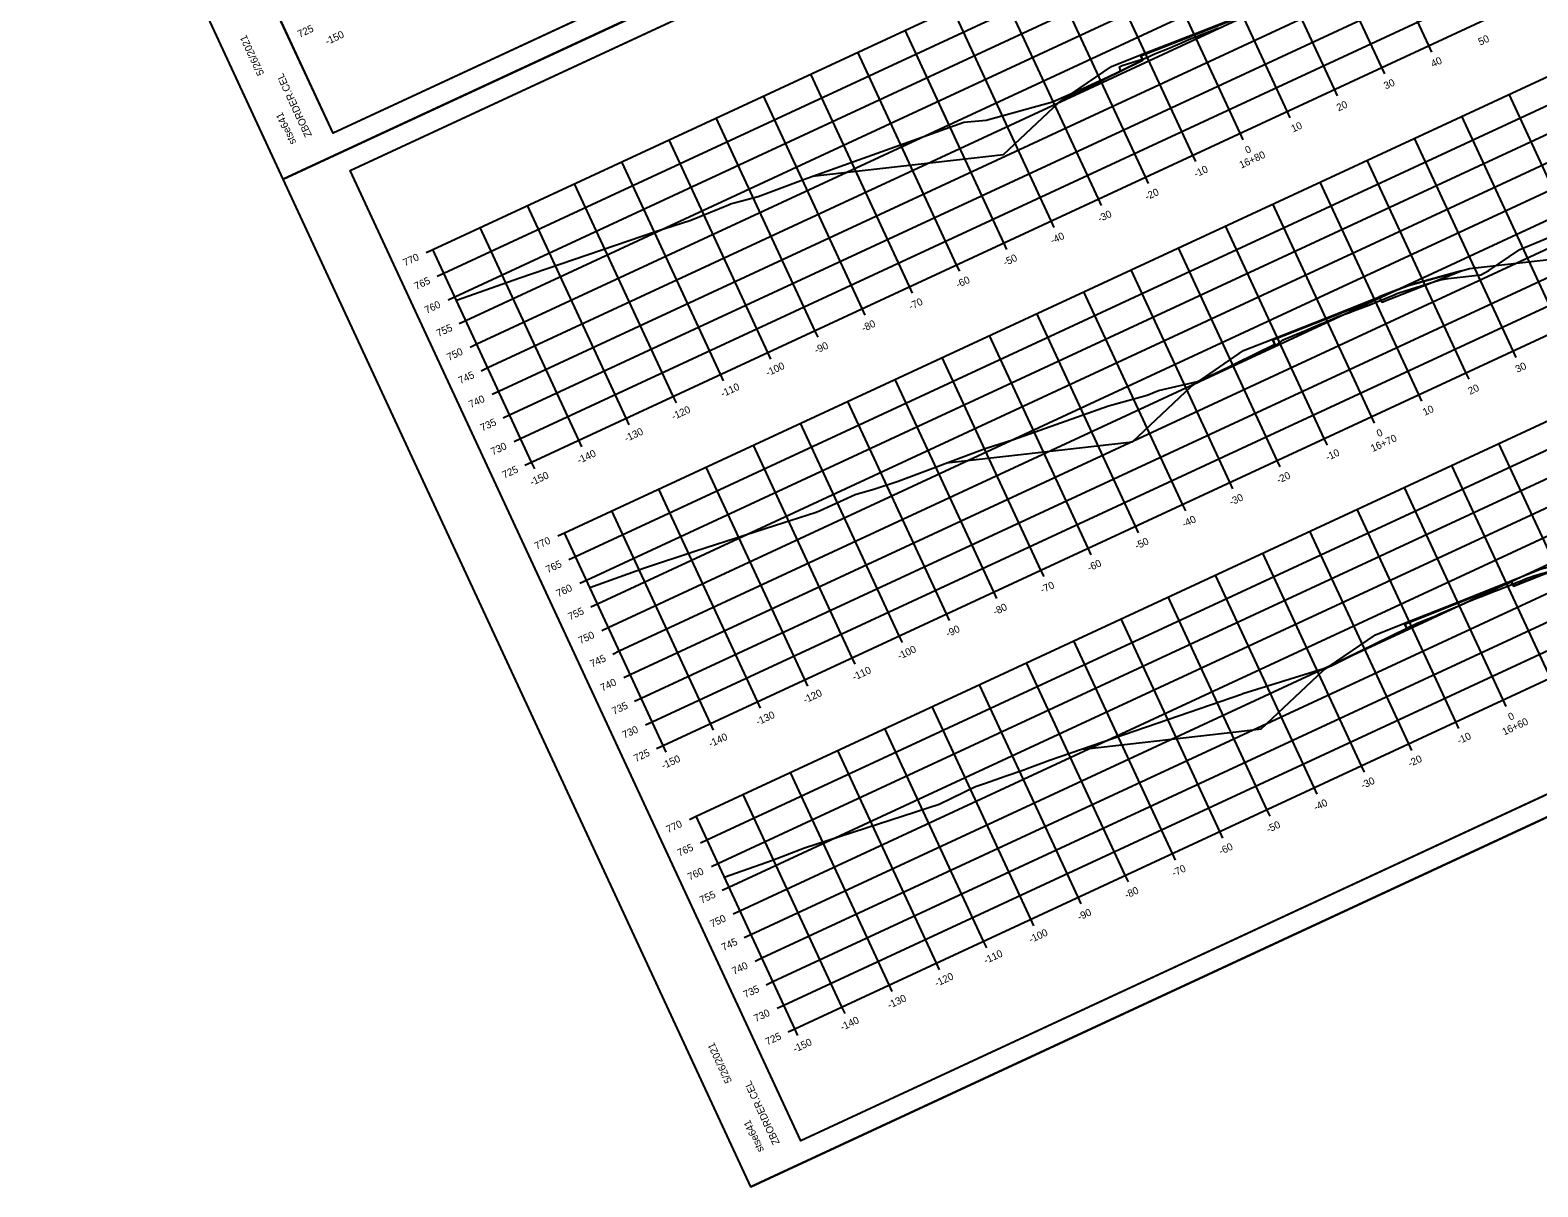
# Model space of a CAD drawing. Extents: x 1354696 to 1366163, y 660729 to 670380.
# Drawn here: x 1358133.8 to 1358423.4, y 665349.1 to 665571.2 of the extents above; entities that cross this region are included whole.
import ezdxf

# ---------------------------------------------------------------- set-up
doc = ezdxf.new("R2010")
doc.units = 0
for name, color, linetype in [('Default', 7, 'Continuous'), ('R_Alt Surface', 7, 'Continuous'), ('R_Axis', 7, 'Continuous'), ('R_Axis Annot', 7, 'Continuous'), ('R_Border', 7, 'Continuous'), ('R_Exist Surface', 7, 'Continuous'), ('R_Fin Surface', 7, 'Continuous'), ('R_Grid', 7, 'Continuous'), ('R_No Plot', 7, 'Continuous')]:
    doc.layers.add(name, color=color, linetype=linetype)

msp = doc.modelspace()

# ---------------------------------------------------------------- linework, layer by layer
at = {"layer": 'Default'}
for points in [[(1358347.17, 665566.29), (1358347.56, 665565.42), (1358332.31, 665557.97), (1358341.5, 665564.25), (1358347.1, 665566.45)], [(1358393.01, 665519.8), (1358393.42, 665518.94), (1358408.71, 665524.98), (1358398.53, 665522.17), (1358392.94, 665519.96)], [(1358372.51, 665511.72), (1358372.9, 665510.85), (1358357.75, 665503.44), (1358366.85, 665509.66), (1358372.44, 665511.87)], [(1358418.73, 665464.43), (1358418.32, 665465.29), (1358418.25, 665465.44), (1358423.83, 665467.67), (1358433.77, 665470.41)], [(1358397.84, 665457.15), (1358398.23, 665456.28), (1358383.18, 665448.92), (1358392.19, 665455.08), (1358397.77, 665457.3)]]:
    msp.add_lwpolyline(points, close=True, dxfattribs=at)
at = {"layer": 'R_Alt Surface'}
for points in [[(1358332.31, 665557.97), (1358347.56, 665565.42), (1358347.17, 665566.29), (1358357.43, 665570.31), (1358367.69, 665574.33), (1358368.1, 665573.47), (1358383.66, 665579.56)], [(1358357.75, 665503.44), (1358372.9, 665510.85), (1358372.51, 665511.72), (1358382.76, 665515.76), (1358393.01, 665519.8), (1358393.42, 665518.94), (1358408.71, 665524.98)], [(1358383.18, 665448.92), (1358398.23, 665456.28), (1358397.84, 665457.15), (1358408.08, 665461.22), (1358418.32, 665465.29), (1358418.73, 665464.43), (1358433.77, 665470.41)]]:
    msp.add_lwpolyline(points, dxfattribs=at)
at = {"layer": 'R_Axis'}
for p, q in [((1358230.15, 665488.26), (1358502.25, 665614.59)), ((1358403.07, 665567), (1358402.48, 665568.27)), ((1358394, 665562.79), (1358393.41, 665564.06)), ((1358255.41, 665433.84), (1358527.52, 665560.17)), ((1358384.93, 665558.58), (1358384.34, 665559.85)), ((1358375.86, 665554.37), (1358375.27, 665555.64)), ((1358366.79, 665550.16), (1358366.2, 665551.43)), ((1358357.72, 665545.95), (1358357.13, 665547.22)), ((1358348.65, 665541.74), (1358348.06, 665543.01)), ((1358339.58, 665537.53), (1358338.99, 665538.8)), ((1358330.51, 665533.31), (1358329.92, 665534.58)), ((1358209.93, 665528.49), (1358211.2, 665529.08)), ((1358230.15, 665488.26), (1358211.2, 665529.08)), ((1358321.44, 665529.1), (1358320.85, 665530.37)), ((1358312.37, 665524.89), (1358311.78, 665526.16)), ((1358212.03, 665523.95), (1358213.3, 665524.54)), ((1358214.14, 665519.42), (1358215.41, 665520.01)), ((1358303.3, 665520.68), (1358302.71, 665521.95)), ((1358294.23, 665516.47), (1358293.64, 665517.74)), ((1358216.24, 665514.88), (1358217.51, 665515.47)), ((1358218.35, 665510.35), (1358219.62, 665510.94)), ((1358285.16, 665512.26), (1358284.57, 665513.53)), ((1358276.09, 665508.05), (1358275.5, 665509.32)), ((1358419.26, 665508.37), (1358418.67, 665509.64)), ((1358220.45, 665505.81), (1358221.72, 665506.4)), ((1358267.02, 665503.84), (1358266.43, 665505.11)), ((1358280.68, 665379.42), (1358552.78, 665505.75)), ((1358410.19, 665504.16), (1358409.6, 665505.43)), ((1358222.56, 665501.28), (1358223.83, 665501.87)), ((1358257.95, 665499.63), (1358257.36, 665500.9)), ((1358401.12, 665499.95), (1358400.53, 665501.22)), ((1358224.66, 665496.74), (1358225.93, 665497.33)), ((1358248.88, 665495.42), (1358248.29, 665496.69)), ((1358392.05, 665495.74), (1358391.46, 665497.01)), ((1358226.77, 665492.21), (1358228.04, 665492.8)), ((1358239.81, 665491.2), (1358239.22, 665492.47)), ((1358382.98, 665491.53), (1358382.39, 665492.8)), ((1358228.88, 665487.67), (1358230.15, 665488.26)), ((1358230.74, 665486.99), (1358230.15, 665488.26)), ((1358373.91, 665487.32), (1358373.32, 665488.59)), ((1358364.84, 665483.1), (1358364.25, 665484.37)), ((1358355.77, 665478.89), (1358355.18, 665480.16)), ((1358346.7, 665474.68), (1358346.11, 665475.95)), ((1358235.19, 665474.07), (1358236.46, 665474.66)), ((1358255.41, 665433.84), (1358236.46, 665474.66)), ((1358237.3, 665469.53), (1358238.57, 665470.12)), ((1358337.63, 665470.47), (1358337.04, 665471.74)), ((1358328.56, 665466.26), (1358327.97, 665467.53)), ((1358239.4, 665465), (1358240.67, 665465.59)), ((1358319.49, 665462.05), (1358318.9, 665463.32)), ((1358241.51, 665460.46), (1358242.78, 665461.05)), ((1358310.42, 665457.84), (1358309.83, 665459.11)), ((1358243.61, 665455.93), (1358244.88, 665456.52)), ((1358301.35, 665453.63), (1358300.76, 665454.9)), ((1358245.72, 665451.39), (1358246.99, 665451.98)), ((1358292.28, 665449.42), (1358291.69, 665450.69)), ((1358247.83, 665446.86), (1358249.1, 665447.45)), ((1358283.21, 665445.21), (1358282.62, 665446.48)), ((1358249.93, 665442.32), (1358251.2, 665442.91)), ((1358274.14, 665440.99), (1358273.55, 665442.26)), ((1358417.32, 665441.32), (1358416.73, 665442.59)), ((1358252.04, 665437.79), (1358253.31, 665438.38)), ((1358408.25, 665437.11), (1358407.66, 665438.38)), ((1358265.07, 665436.78), (1358264.48, 665438.05)), ((1358254.14, 665433.25), (1358255.41, 665433.84)), ((1358256, 665432.57), (1358255.41, 665433.84)), ((1358399.18, 665432.89), (1358398.59, 665434.16)), ((1358390.11, 665428.68), (1358389.52, 665429.95)), ((1358381.04, 665424.47), (1358380.45, 665425.74)), ((1358371.97, 665420.26), (1358371.38, 665421.53)), ((1358260.46, 665419.65), (1358261.73, 665420.24)), ((1358280.68, 665379.42), (1358261.73, 665420.24)), ((1358262.56, 665415.11), (1358263.83, 665415.7)), ((1358362.9, 665416.05), (1358362.31, 665417.32)), ((1358353.83, 665411.84), (1358353.24, 665413.11)), ((1358264.67, 665410.58), (1358265.94, 665411.17)), ((1358266.77, 665406.04), (1358268.04, 665406.63)), ((1358344.76, 665407.63), (1358344.17, 665408.9)), ((1358335.69, 665403.42), (1358335.1, 665404.69)), ((1358268.88, 665401.51), (1358270.15, 665402.1)), ((1358326.62, 665399.21), (1358326.03, 665400.48)), ((1358270.99, 665396.97), (1358272.26, 665397.56)), ((1358317.55, 665395), (1358316.96, 665396.27)), ((1358273.09, 665392.44), (1358274.36, 665393.03)), ((1358308.48, 665390.78), (1358307.89, 665392.05)), ((1358275.2, 665387.9), (1358276.47, 665388.49)), ((1358299.41, 665386.57), (1358298.82, 665387.84)), ((1358277.3, 665383.37), (1358278.57, 665383.96)), ((1358290.34, 665382.36), (1358289.75, 665383.63)), ((1358279.41, 665378.83), (1358280.68, 665379.42)), ((1358281.27, 665378.15), (1358280.68, 665379.42))]:
    msp.add_line(p, q, dxfattribs=at)
at = {"layer": 'R_Border'}
for p, q in [((1358192.01, 665551.41), (1358105.49, 665737.77)), ((1358478.79, 665684.56), (1358192.01, 665551.41)), ((1358195.32, 665544.27), (1358482.1, 665677.41)), ((1358192.01, 665551.41), (1358192.01, 665551.41)), ((1358281.84, 665357.91), (1358195.32, 665544.27)), ((1358568.62, 665491.06), (1358281.84, 665357.91)), ((1358281.84, 665357.91), (1358281.84, 665357.91))]:
    msp.add_line(p, q, dxfattribs=at)
at = {"layer": 'R_Exist Surface'}
for points in [[(1358215.7, 665519.38), (1358227.87, 665523.63), (1358253.93, 665532.54), (1358260.75, 665534.73), (1358267.94, 665537.66), (1358268.36, 665537.85), (1358269.04, 665538.06), (1358273.67, 665539.28), (1358282.39, 665542.55), (1358313.18, 665553.52), (1358317.48, 665553.9), (1358330.2, 665557.41), (1358336.15, 665560.04), (1358343.27, 665563.31), (1358343.05, 665564.14), (1358343.55, 665564.41), (1358347.84, 665565.78), (1358348.61, 665566.1), (1358349.26, 665566.43), (1358350, 665566.71), (1358352.58, 665567.74), (1358353.75, 665568.23), (1358354.94, 665568.74), (1358356.5, 665569.44), (1358357.69, 665569.94), (1358359.28, 665570.58), (1358360.5, 665571.03), (1358362.08, 665571.67)], [(1358241.33, 665464.17), (1358251.85, 665467.97), (1358261.71, 665471.19), (1358276.78, 665476.05), (1358284.79, 665478.65), (1358285.56, 665478.96), (1358292.3, 665482), (1358296.05, 665483.13), (1358300.56, 665484.59), (1358317.26, 665490.89), (1358322.72, 665492.58), (1358340.92, 665499.08), (1358348.38, 665501.13), (1358350.53, 665501.99), (1358358.04, 665503.76), (1358372.98, 665510.66), (1358373.34, 665510.84), (1358374.47, 665511.75), (1358374.6, 665511.82), (1358376.17, 665512.43), (1358376.57, 665512.6), (1358379.09, 665513.66), (1358379.34, 665513.77), (1358381.85, 665514.85), (1358382.1, 665514.96), (1358384.61, 665516.02), (1358384.87, 665516.13), (1358387.43, 665517.07), (1358387.7, 665517.18), (1358390.24, 665518.14), (1358390.63, 665518.29), (1358394.39, 665519.81), (1358395.79, 665520.39), (1358396.31, 665520.6), (1358396.68, 665520.75), (1358397.91, 665521.12), (1358403.2, 665522.81), (1358404.66, 665523.23), (1358406.19, 665523.51), (1358412.44, 665524.23), (1358413.96, 665525.07), (1358419.96, 665529.06), (1358440.81, 665537.78)], [(1358267.16, 665408.54), (1358276.39, 665411.82), (1358282.57, 665414.19), (1358308.44, 665422.56), (1358315.39, 665425.97), (1358316.76, 665426.39), (1358317.3, 665426.6), (1358321.07, 665427.95), (1358324.68, 665429.17), (1358325.35, 665429.39), (1358329.62, 665431), (1358366.68, 665443.78), (1358366.72, 665443.79), (1358366.72, 665443.79), (1358383.04, 665448.87), (1358383.72, 665449.11), (1358385.52, 665450.03), (1358398.44, 665456.4), (1358398.64, 665456.55), (1358399.81, 665457.14), (1358400.2, 665457.29), (1358403.73, 665458.76), (1358404.37, 665459.03), (1358406.48, 665459.92), (1358407.13, 665460.21), (1358409.22, 665461.11), (1358409.89, 665461.39), (1358412, 665462.23), (1358412.69, 665462.49), (1358414.78, 665463.33), (1358415.48, 665463.6), (1358418.38, 665464.74), (1358419.45, 665465.17), (1358420.02, 665465.41), (1358421.35, 665465.97), (1358422.83, 665466.45), (1358430.36, 665468.61)]]:
    msp.add_lwpolyline(points, dxfattribs=at)
at = {"layer": 'R_Fin Surface'}
for points in [[(1358284.04, 665543.14), (1358320.77, 665547.3), (1358331.46, 665557.39), (1358332.31, 665557.97), (1358341.5, 665564.25), (1358347.1, 665566.45), (1358357.36, 665570.46), (1358367.62, 665574.48), (1358373.22, 665576.68), (1358383.66, 665579.56), (1358384.94, 665579.92), (1358399.64, 665581.58), (1358408.22, 665589.67)], [(1358309.93, 665488.13), (1358310.38, 665488.18), (1358318.89, 665489.14), (1358320.62, 665489.34), (1358345.54, 665492.17), (1358356.8, 665502.8), (1358357.75, 665503.44), (1358366.85, 665509.66), (1358372.44, 665511.87), (1358382.69, 665515.91), (1358392.94, 665519.96), (1358398.53, 665522.17), (1358408.71, 665524.98), (1358410.25, 665525.4), (1358426.1, 665527.2), (1358434.53, 665535.15)], [(1358335.69, 665433.1), (1358336.72, 665433.22), (1358365.98, 665436.53), (1358370.28, 665437.02), (1358382.14, 665448.21), (1358382.14, 665448.21), (1358383.18, 665448.92), (1358392.19, 665455.08), (1358397.77, 665457.3), (1358408.01, 665461.37), (1358418.25, 665465.44), (1358423.83, 665467.67), (1358433.77, 665470.41), (1358435.56, 665470.9), (1358435.56, 665470.9), (1358452.6, 665472.84), (1358461.11, 665480.87)]]:
    msp.add_lwpolyline(points, dxfattribs=at)
at = {"layer": 'R_Grid'}
for p, q in [((1358211.2, 665529.08), (1358483.3, 665655.41)), ((1358213.3, 665524.54), (1358485.41, 665650.87)), ((1358215.41, 665520.01), (1358487.51, 665646.34)), ((1358217.51, 665515.47), (1358489.62, 665641.8)), ((1358219.62, 665510.94), (1358491.72, 665637.27)), ((1358221.72, 665506.4), (1358493.83, 665632.73)), ((1358223.83, 665501.87), (1358495.93, 665628.2)), ((1358225.93, 665497.33), (1358498.04, 665623.66)), ((1358228.04, 665492.8), (1358500.14, 665619.13)), ((1358230.15, 665488.26), (1358502.25, 665614.59)), ((1358402.48, 665568.27), (1358383.53, 665609.09)), ((1358393.41, 665564.06), (1358374.46, 665604.88)), ((1358236.46, 665474.66), (1358508.57, 665600.99)), ((1358384.34, 665559.85), (1358365.39, 665600.67)), ((1358238.57, 665470.12), (1358510.67, 665596.45)), ((1358375.27, 665555.64), (1358356.32, 665596.46)), ((1358240.67, 665465.59), (1358512.78, 665591.92)), ((1358366.2, 665551.43), (1358347.25, 665592.24)), ((1358242.78, 665461.05), (1358514.88, 665587.38)), ((1358357.13, 665547.22), (1358338.18, 665588.03)), ((1358348.06, 665543.01), (1358329.11, 665583.82)), ((1358244.88, 665456.52), (1358516.99, 665582.85)), ((1358246.99, 665451.98), (1358519.09, 665578.31)), ((1358338.99, 665538.8), (1358320.04, 665579.61)), ((1358329.92, 665534.58), (1358310.97, 665575.4)), ((1358249.1, 665447.45), (1358521.2, 665573.78)), ((1358251.2, 665442.91), (1358523.3, 665569.24)), ((1358320.85, 665530.37), (1358301.9, 665571.19)), ((1358311.78, 665526.16), (1358292.83, 665566.98)), ((1358253.31, 665438.38), (1358525.41, 665564.71)), ((1358302.71, 665521.95), (1358283.76, 665562.77)), ((1358255.41, 665433.84), (1358527.52, 665560.17)), ((1358293.64, 665517.74), (1358274.69, 665558.56)), ((1358436.81, 665518.06), (1358417.86, 665558.88)), ((1358284.57, 665513.53), (1358265.62, 665554.34)), ((1358427.74, 665513.85), (1358408.79, 665554.67)), ((1358275.5, 665509.32), (1358256.55, 665550.13)), ((1358418.67, 665509.64), (1358399.72, 665550.46)), ((1358266.43, 665505.11), (1358247.48, 665545.92)), ((1358261.73, 665420.24), (1358533.83, 665546.57)), ((1358409.6, 665505.43), (1358390.65, 665546.25)), ((1358257.36, 665500.9), (1358238.41, 665541.71)), ((1358263.83, 665415.7), (1358535.94, 665542.03)), ((1358400.53, 665501.22), (1358381.58, 665542.03)), ((1358248.29, 665496.69), (1358229.34, 665537.5)), ((1358265.94, 665411.17), (1358538.04, 665537.5)), ((1358391.46, 665497.01), (1358372.51, 665537.82)), ((1358239.22, 665492.47), (1358220.27, 665533.29)), ((1358268.04, 665406.63), (1358540.15, 665532.96)), ((1358382.39, 665492.8), (1358363.44, 665533.61)), ((1358230.15, 665488.26), (1358211.2, 665529.08)), ((1358270.15, 665402.1), (1358542.25, 665528.43)), ((1358373.32, 665488.59), (1358354.37, 665529.4)), ((1358364.25, 665484.37), (1358345.3, 665525.19)), ((1358272.26, 665397.56), (1358544.36, 665523.89)), ((1358274.36, 665393.03), (1358546.47, 665519.36)), ((1358355.18, 665480.16), (1358336.23, 665520.98)), ((1358346.11, 665475.95), (1358327.16, 665516.77)), ((1358276.47, 665388.49), (1358548.57, 665514.82)), ((1358337.04, 665471.74), (1358318.09, 665512.56)), ((1358278.57, 665383.96), (1358550.68, 665510.29)), ((1358327.97, 665467.53), (1358309.02, 665508.35)), ((1358280.68, 665379.42), (1358552.78, 665505.75)), ((1358318.9, 665463.32), (1358299.95, 665504.14)), ((1358309.83, 665459.11), (1358290.88, 665499.92)), ((1358300.76, 665454.9), (1358281.81, 665495.71)), ((1358291.69, 665450.69), (1358272.74, 665491.5)), ((1358434.87, 665451.01), (1358415.92, 665491.82)), ((1358425.8, 665446.8), (1358406.85, 665487.61)), ((1358282.62, 665446.48), (1358263.67, 665487.29)), ((1358273.55, 665442.26), (1358254.6, 665483.08)), ((1358416.73, 665442.59), (1358397.78, 665483.4)), ((1358264.48, 665438.05), (1358245.53, 665478.87)), ((1358407.66, 665438.38), (1358388.71, 665479.19)), ((1358255.41, 665433.84), (1358236.46, 665474.66)), ((1358398.59, 665434.16), (1358379.64, 665474.98)), ((1358389.52, 665429.95), (1358370.57, 665470.77)), ((1358380.45, 665425.74), (1358361.5, 665466.56)), ((1358371.38, 665421.53), (1358352.43, 665462.35)), ((1358362.31, 665417.32), (1358343.36, 665458.14)), ((1358353.24, 665413.11), (1358334.29, 665453.93)), ((1358344.17, 665408.9), (1358325.22, 665449.71)), ((1358335.1, 665404.69), (1358316.15, 665445.5)), ((1358326.03, 665400.48), (1358307.08, 665441.29)), ((1358316.96, 665396.27), (1358298.01, 665437.08)), ((1358307.89, 665392.05), (1358288.94, 665432.87)), ((1358298.82, 665387.84), (1358279.87, 665428.66)), ((1358289.75, 665383.63), (1358270.8, 665424.45)), ((1358280.68, 665379.42), (1358261.73, 665420.24))]:
    msp.add_line(p, q, dxfattribs=at)
at = {"layer": 'R_No Plot'}
for p, q in [((1358182.43, 665542.58), (1358484.77, 665682.95)), ((1358182.44, 665542.58), (1358484.77, 665682.95)), ((1358272.27, 665349.08), (1358574.61, 665489.45))]:
    msp.add_line(p, q, dxfattribs=at)
for points in [[(1358092.59, 665736.08), (1358394.94, 665876.45), (1358484.77, 665682.95), (1358182.43, 665542.58)], [(1358317.66, 665836.27), (1358335.45, 665844.53), (1358339.61, 665835.57), (1358354.23, 665842.36), (1358375.27, 665852.13), (1358387.23, 665826.64), (1358408.28, 665836.41), (1358478.79, 665684.56), (1358192.01, 665551.41), (1358105.49, 665737.77)], [(1358182.43, 665542.58), (1358484.77, 665682.95), (1358574.61, 665489.45), (1358272.27, 665349.08)], [(1358407.49, 665642.77), (1358425.29, 665651.03), (1358429.45, 665642.07), (1358444.06, 665648.86), (1358465.1, 665658.63), (1358477.07, 665633.14), (1358498.12, 665642.91), (1358568.62, 665491.06), (1358281.84, 665357.91), (1358195.32, 665544.27)]]:
    msp.add_lwpolyline(points, close=True, dxfattribs=at)

# ---------------------------------------------------------------- texts
at = {"layer": 'R_Axis Annot'}
for s, p in [('725', (1358185.6, 665569.72)), ('-150', (1358190.89, 665568.32)), ('50', (1358412.33, 665568.22)), ('40', (1358403.26, 665564.01)), ('30', (1358394.19, 665559.79)), ('20', (1358385.12, 665555.58)), ('10', (1358376.41, 665551.54)), ('0', (1358367.55, 665547.43)), ('16+80', (1358366.44, 665544.59)), ('-10', (1358357.75, 665542.88)), ('-20', (1358348.32, 665538.5)), ('-30', (1358339.25, 665534.29)), ('-40', (1358330.18, 665530.08)), ('770', (1358205.84, 665525.82)), ('-50', (1358321.11, 665525.87)), ('765', (1358208, 665521.31)), ('-60', (1358312.01, 665521.64)), ('-70', (1358302.97, 665517.44)), ('760', (1358209.99, 665516.72)), ('755', (1358212.27, 665512.27)), ('-80', (1358293.9, 665513.23)), ('-90', (1358284.83, 665509.02)), ('750', (1358214.26, 665507.68)), ('745', (1358216.48, 665503.2)), ('-100', (1358275.5, 665504.69)), ('30', (1358419.46, 665505.37)), ('-110', (1358266.84, 665500.67)), ('20', (1358410.39, 665501.16)), ('740', (1358218.47, 665498.61)), ('10', (1358401.68, 665497.12)), ('735', (1358220.69, 665494.13)), ('-120', (1358257.41, 665496.29)), ('-130', (1358248.34, 665492.08)), ('16+70', (1358391.7, 665490.17)), ('0', (1358392.82, 665493.01)), ('730', (1358222.69, 665489.54)), ('-140', (1358239.27, 665487.87)), ('-10', (1358383.02, 665488.46)), ('725', (1358224.9, 665485.06)), ('-150', (1358230.2, 665483.66)), ('-20', (1358373.59, 665484.08)), ('-30', (1358364.52, 665479.87)), ('-40', (1358355.45, 665475.66)), ('770', (1358231.11, 665471.4)), ('-50', (1358346.38, 665471.44)), ('765', (1358233.26, 665466.89)), ('-60', (1358337.28, 665467.22)), ('760', (1358235.26, 665462.3)), ('-70', (1358328.24, 665463.02)), ('755', (1358237.53, 665457.85)), ('-80', (1358319.17, 665458.81)), ('750', (1358239.53, 665453.26)), ('-90', (1358310.1, 665454.6)), ('-100', (1358300.77, 665450.27)), ('745', (1358241.75, 665448.78)), ('-110', (1358292.11, 665446.25)), ('740', (1358243.74, 665444.19)), ('-120', (1358282.68, 665441.87)), ('735', (1358245.96, 665439.71)), ('-130', (1358273.61, 665437.66)), ('16+60', (1358416.94, 665435.74)), ('0', (1358418.08, 665438.58)), ('730', (1358247.95, 665435.12)), ('-140', (1358264.54, 665433.45)), ('-10', (1358408.28, 665434.03)), ('725', (1358250.17, 665430.64)), ('-150', (1358255.47, 665429.24)), ('-20', (1358398.85, 665429.66)), ('-30', (1358389.78, 665425.45)), ('-40', (1358380.71, 665421.23)), ('770', (1358256.37, 665416.98)), ('-50', (1358371.64, 665417.02)), ('-60', (1358362.54, 665412.8)), ('765', (1358258.53, 665412.47)), ('760', (1358260.52, 665407.88)), ('-70', (1358353.5, 665408.6)), ('-80', (1358344.43, 665404.39)), ('755', (1358262.8, 665403.43)), ('750', (1358264.8, 665398.84)), ('-90', (1358335.36, 665400.18)), ('-100', (1358326.03, 665395.85)), ('745', (1358267.01, 665394.36)), ('740', (1358269.01, 665389.77)), ('-110', (1358317.37, 665391.83)), ('-120', (1358307.94, 665387.45)), ('735', (1358271.22, 665385.29)), ('-130', (1358298.87, 665383.24)), ('730', (1358273.22, 665380.7)), ('-140', (1358289.8, 665379.03)), ('725', (1358275.43, 665376.21)), ('-150', (1358280.73, 665374.82))]:
    msp.add_text(s, height=1.4, rotation=24.9042, dxfattribs=at).set_placement(p)
at = {"layer": 'R_Border'}
for s, p in [('5/26/2021', (1358178.83, 665562.85)), ('ZBORDER.CEL', (1358187.99, 665551.01)), ('stse641', (1358184.98, 665549.61)), ('5/26/2021', (1358268.67, 665369.35)), ('ZBORDER.CEL', (1358277.83, 665357.51)), ('stse641', (1358274.81, 665356.11))]:
    msp.add_text(s, height=1.4, rotation=114.9042, dxfattribs=at).set_placement(p)

doc.saveas('drawing.dxf')
